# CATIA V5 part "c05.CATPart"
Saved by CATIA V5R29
Part number: c05
Bounding box of the stored display mesh (mm): x 16.662 to 134.073, y -101 to 75, z 102.292 to 225.053
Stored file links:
  C:\Users\제5강의실-23\Desktop\c05.CATPart
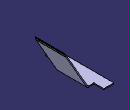
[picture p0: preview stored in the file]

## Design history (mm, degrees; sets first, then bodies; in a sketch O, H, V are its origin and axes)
Body1 (main body)
  DatumCurve1
  DatumSurface1
  DatumSurface2
  Sketch1 on zx-plane, origin (0, 0, 0), H (-1, 0, 0), V (0, 0, 1)
    line L1 (-136.6713, 223.5526) -> (-66.6616, 102.2922)
    line L2 (-66.6616, 102.2922) -> (-16.6616, 102.2922)
    line L3 (-16.6616, 102.2922) -> (-16.6616, 105.2922)
    line L4 (-16.6616, 105.2922) -> (-64.9296, 105.2922)
    line L5 (-64.9296, 105.2922) -> (-134.0732, 225.0526)
    point P6 (-134.0732, 225.0526)
    line L6 (-134.0732, 225.0526) -> (-136.6713, 223.5526)
    reference projected point E1 (-36.6616, 12.2922) from edge of DatumCurve1
    reference intersected line E2 through (0, 102.2922) direction (-1, 0) from face of DatumSurface1
    reference intersected line E3 through (-16.6616, 0) direction (0, 1) from face of DatumSurface2
    length L6 = 3
    length L3 = 3
    length L2 = 50
    angle L1 L2 = 120
    distance P6 E1 = 234
    distance L2 E2 = 0
    horizontal: L2 H, L4 H
    vertical: L3 V
    parallelism: L5 L1
    perpendicularity: L6 L1
    coincidence: L3 E3
  Pad1: profile Sketch1, direction (0, 1, 0), length 45, mirrored extent
  DatumSurface3
  DatumSurface4
  Sketch2 on face of Pad1 from Sketch1.L4, origin (0, 0, 105.2922), H (1, 0, 0), V (0, 1, 0)
    line L1 (46.6616, -101) -> (16.6616, -101)
    line L2 (16.6616, -101) -> (16.6616, -45)
    line L3 (16.6616, -45) -> (46.6616, -45)
    line L4 (46.6616, -45) -> (46.6616, -101)
    reference projected line E1 (16.6616, -45) -> (64.9296, -45) from edge [start face of Pad1 | face of Pad1 from Sketch1.L4]
    reference intersected line E2 through (0, -101) direction (1, 0) from face of DatumSurface3
    reference projected line E3 (16.6616, -45) -> (16.6616, 45) from edge [face of Pad1 from Sketch1.L4 | face of Pad1 from Sketch1.L3]
    point P5 (16.6616, 45)
    line L5 (16.6616, 45) -> (46.6616, 45)
    line L6 (46.6616, 45) -> (46.6616, 75)
    line L7 (46.6616, 75) -> (16.6616, 75)
    line L8 (16.6616, 75) -> (16.6616, 45)
    reference intersected line E4 (16.6616, 45) -> (68.3937, 45) from end face of Pad1
    reference intersected line E5 through (0, 75) direction (-1, 0) from face of DatumSurface4
    distance E2 L1 = 0
    distance L2 E3 = 0
    length L1 = 30
    horizontal: L1 H, L3 H, L5 H, L7 H
    vertical: L2 V, L4 V, L6 V, L8 V
    coincidence: L3 E1, P5 L2, L5 E4, L7 E5, L6 L4
  Pad2: profile Sketch2, direction (0, 0, -1), length 3
  Sketch3 on end face of Pad1, origin (0, 45, 0), H (-1, 0, 0), V (0, 0, 1)
    point P1 (-134.0732, 225.0526)
    line L1 (-134.0732, 225.0526) -> (-131.6713, 214.8924)
    line L2 (-131.6713, 214.8924) -> (-136.6713, 223.5526)
    line L3 (-136.6713, 223.5526) -> (-134.0732, 225.0526)
    reference intersected line E1 (-136.6713, 223.5526) -> (-134.0732, 225.0526) from face of Pad1 from Sketch1.L6
    reference intersected line E2 (-66.6616, 102.2922) -> (-136.6713, 223.5526) from face of Pad1 from Sketch1.L1
    reference intersected line E3 (-134.0732, 225.0526) -> (-64.9296, 105.2922) from face of Pad1 from Sketch1.L5
    length L2 = 10
    coincidence: L3 E1, E2 L2, P1 E3
  Pocket1: profile Sketch3, direction (0, -1, 0), through (limit type 3)
  Sketch4 on face of Pad1 from Sketch1.L1, origin (5.7024, 0, -3.2923), H (0, 1, 0), V (0.5, 0, 0.866)
    point P1 (-45, 261.9379)
    line L1 (-45, 261.9379) -> (-43, 255.9379)
    point P2 (-43, 255.9379)
    line L2 (-43, 255.9379) -> (-43, 261.9379)
    point P3 (-43, 261.9379)
    reference projected line E1 (45, 261.9379) -> (-45, 261.9379) from edge [face of Pad1 from Sketch1.L5 | face of Pocket1 from Sketch3.L1]
    reference projected line E2 (45, 261.9379) -> (-45, 261.9379) from edge [face of Pad1 from Sketch1.L5 | face of Pocket1 from Sketch3.L1]
    reference intersected line E3 (-45, 121.9185) -> (-45, 261.9379) from start face of Pad1
    point P4 (-41, 261.9379)
    point P5 (-41, 255.9379)
    line L3 (-41, 255.9379) -> (-41, 261.9379)
    point P6 (-43, 261.9379)
    line L4 (-43, 261.9379) -> (-41, 255.9379)
    point P7 (-39, 261.9379)
    line L5 (-39, 255.9379) -> (-39, 261.9379)
    point P9 (-41, 261.9379)
    line L6 (-41, 261.9379) -> (-39, 255.9379)
    point P10 (-37, 261.9379)
    line L7 (-37, 255.9379) -> (-37, 261.9379)
    point P12 (-39, 261.9379)
    line L8 (-39, 261.9379) -> (-37, 255.9379)
    point P13 (-35, 261.9379)
    line L9 (-35, 255.9379) -> (-35, 261.9379)
    point P15 (-37, 261.9379)
    line L10 (-37, 261.9379) -> (-35, 255.9379)
    point P16 (-33, 261.9379)
    line L11 (-33, 255.9379) -> (-33, 261.9379)
    point P18 (-35, 261.9379)
    line L12 (-35, 261.9379) -> (-33, 255.9379)
    point P19 (-31, 261.9379)
    line L13 (-31, 255.9379) -> (-31, 261.9379)
    point P21 (-33, 261.9379)
    line L14 (-33, 261.9379) -> (-31, 255.9379)
    point P22 (-29, 261.9379)
    line L15 (-29, 255.9379) -> (-29, 261.9379)
    point P24 (-31, 261.9379)
    line L16 (-31, 261.9379) -> (-29, 255.9379)
    point P25 (-27, 261.9379)
    line L17 (-27, 255.9379) -> (-27, 261.9379)
    point P27 (-29, 261.9379)
    line L18 (-29, 261.9379) -> (-27, 255.9379)
    point P28 (-25, 261.9379)
    line L19 (-25, 255.9379) -> (-25, 261.9379)
    point P30 (-27, 261.9379)
    line L20 (-27, 261.9379) -> (-25, 255.9379)
    point P31 (-23, 261.9379)
    line L21 (-23, 255.9379) -> (-23, 261.9379)
    point P33 (-25, 261.9379)
    line L22 (-25, 261.9379) -> (-23, 255.9379)
    point P34 (-21, 261.9379)
    line L23 (-21, 255.9379) -> (-21, 261.9379)
    point P36 (-23, 261.9379)
    line L24 (-23, 261.9379) -> (-21, 255.9379)
    point P37 (-19, 261.9379)
    line L25 (-19, 255.9379) -> (-19, 261.9379)
    point P39 (-21, 261.9379)
    line L26 (-21, 261.9379) -> (-19, 255.9379)
    point P40 (-17, 261.9379)
    line L27 (-17, 255.9379) -> (-17, 261.9379)
    point P42 (-19, 261.9379)
    line L28 (-19, 261.9379) -> (-17, 255.9379)
    point P43 (-15, 261.9379)
    line L29 (-15, 255.9379) -> (-15, 261.9379)
    point P45 (-17, 261.9379)
    line L30 (-17, 261.9379) -> (-15, 255.9379)
    point P46 (-13, 261.9379)
    line L31 (-13, 255.9379) -> (-13, 261.9379)
    point P48 (-15, 261.9379)
    line L32 (-15, 261.9379) -> (-13, 255.9379)
    point P49 (-11, 261.9379)
    line L33 (-11, 255.9379) -> (-11, 261.9379)
    point P51 (-13, 261.9379)
    line L34 (-13, 261.9379) -> (-11, 255.9379)
    point P52 (-9, 261.9379)
    line L35 (-9, 255.9379) -> (-9, 261.9379)
    point P54 (-11, 261.9379)
    line L36 (-11, 261.9379) -> (-9, 255.9379)
    point P55 (-7, 261.9379)
    line L37 (-7, 255.9379) -> (-7, 261.9379)
    point P57 (-9, 261.9379)
    line L38 (-9, 261.9379) -> (-7, 255.9379)
    point P58 (-5, 261.9379)
    line L39 (-5, 255.9379) -> (-5, 261.9379)
    point P60 (-7, 261.9379)
    line L40 (-7, 261.9379) -> (-5, 255.9379)
    point P61 (-3, 261.9379)
    line L41 (-3, 255.9379) -> (-3, 261.9379)
    point P63 (-5, 261.9379)
    line L42 (-5, 261.9379) -> (-3, 255.9379)
    point P64 (-1, 261.9379)
    line L43 (-1, 255.9379) -> (-1, 261.9379)
    point P66 (-3, 261.9379)
    line L44 (-3, 261.9379) -> (-1, 255.9379)
    point P67 (1, 261.9379)
    line L45 (1, 255.9379) -> (1, 261.9379)
    point P69 (-1, 261.9379)
    line L46 (-1, 261.9379) -> (1, 255.9379)
    point P70 (3, 261.9379)
    line L47 (3, 255.9379) -> (3, 261.9379)
    point P72 (1, 261.9379)
    line L48 (1, 261.9379) -> (3, 255.9379)
    point P73 (5, 261.9379)
    line L49 (5, 255.9379) -> (5, 261.9379)
    point P75 (3, 261.9379)
    line L50 (3, 261.9379) -> (5, 255.9379)
    point P76 (7, 261.9379)
    line L51 (7, 255.9379) -> (7, 261.9379)
    point P78 (5, 261.9379)
    line L52 (5, 261.9379) -> (7, 255.9379)
    point P79 (9, 261.9379)
    line L53 (9, 255.9379) -> (9, 261.9379)
    point P81 (7, 261.9379)
    line L54 (7, 261.9379) -> (9, 255.9379)
    point P82 (11, 261.9379)
    line L55 (11, 255.9379) -> (11, 261.9379)
    point P84 (9, 261.9379)
    line L56 (9, 261.9379) -> (11, 255.9379)
    point P85 (13, 261.9379)
    line L57 (13, 255.9379) -> (13, 261.9379)
    point P87 (11, 261.9379)
    line L58 (11, 261.9379) -> (13, 255.9379)
    point P88 (15, 261.9379)
    line L59 (15, 255.9379) -> (15, 261.9379)
    point P90 (13, 261.9379)
    line L60 (13, 261.9379) -> (15, 255.9379)
    point P91 (17, 261.9379)
    line L61 (17, 255.9379) -> (17, 261.9379)
    point P93 (15, 261.9379)
    line L62 (15, 261.9379) -> (17, 255.9379)
    point P94 (19, 261.9379)
    line L63 (19, 255.9379) -> (19, 261.9379)
    point P96 (17, 261.9379)
    line L64 (17, 261.9379) -> (19, 255.9379)
    point P97 (21, 261.9379)
    line L65 (21, 255.9379) -> (21, 261.9379)
    point P99 (19, 261.9379)
    line L66 (19, 261.9379) -> (21, 255.9379)
    point P100 (23, 261.9379)
    line L67 (23, 255.9379) -> (23, 261.9379)
    point P102 (21, 261.9379)
    line L68 (21, 261.9379) -> (23, 255.9379)
    point P103 (25, 261.9379)
    line L69 (25, 255.9379) -> (25, 261.9379)
    point P105 (23, 261.9379)
    line L70 (23, 261.9379) -> (25, 255.9379)
    point P106 (27, 261.9379)
    line L71 (27, 255.9379) -> (27, 261.9379)
    point P108 (25, 261.9379)
    line L72 (25, 261.9379) -> (27, 255.9379)
    point P109 (29, 261.9379)
    line L73 (29, 255.9379) -> (29, 261.9379)
    point P111 (27, 261.9379)
    line L74 (27, 261.9379) -> (29, 255.9379)
    point P112 (31, 261.9379)
    line L75 (31, 255.9379) -> (31, 261.9379)
    point P114 (29, 261.9379)
    line L76 (29, 261.9379) -> (31, 255.9379)
    point P115 (33, 261.9379)
    line L77 (33, 255.9379) -> (33, 261.9379)
    point P117 (31, 261.9379)
    line L78 (31, 261.9379) -> (33, 255.9379)
    point P118 (35, 261.9379)
    line L79 (35, 255.9379) -> (35, 261.9379)
    point P120 (33, 261.9379)
    line L80 (33, 261.9379) -> (35, 255.9379)
    point P121 (37, 261.9379)
    line L81 (37, 255.9379) -> (37, 261.9379)
    point P123 (35, 261.9379)
    line L82 (35, 261.9379) -> (37, 255.9379)
    point P124 (39, 261.9379)
    line L83 (39, 255.9379) -> (39, 261.9379)
    point P126 (37, 261.9379)
    line L84 (37, 261.9379) -> (39, 255.9379)
    point P127 (41, 261.9379)
    line L85 (41, 255.9379) -> (41, 261.9379)
    point P129 (39, 261.9379)
    line L86 (39, 261.9379) -> (41, 255.9379)
    point P130 (43, 261.9379)
    line L87 (43, 255.9379) -> (43, 261.9379)
    point P132 (41, 261.9379)
    line L88 (41, 261.9379) -> (43, 255.9379)
    point P133 (45, 261.9379)
    point P134 (45, 255.9379)
    line L89 (45, 255.9379) -> (45, 269.2814)
    point P135 (43, 261.9379)
    line L90 (43, 261.9379) -> (45, 255.9379)
    point P136 (47, 261.9379)
    point P137 (45, 261.9379)
    point P140 (-45, 261.9379)
    line L91 (-45, 261.9379) -> (-45, 269.2814)
    line L92 (-45, 269.2814) -> (45, 269.2814)
    distance P3 P1 = 2
    distance P4 P6 = 2
    length L5 = 6
    distance P7 P9 = 2
    length L7 = 6
    distance P10 P12 = 2
    length L9 = 6
    distance P13 P15 = 2
    length L11 = 6
    distance P16 P18 = 2
    length L13 = 6
    distance P19 P21 = 2
    length L15 = 6
    distance P22 P24 = 2
    length L17 = 6
    distance P25 P27 = 2
    length L19 = 6
    distance P28 P30 = 2
    length L21 = 6
    distance P31 P33 = 2
    length L23 = 6
    distance P34 P36 = 2
    length L25 = 6
    distance P37 P39 = 2
    length L27 = 6
    distance P40 P42 = 2
    distance P43 P45 = 2
    length L29 = 6
    length L31 = 6
    distance P46 P48 = 2
    length L33 = 6
    distance P49 P51 = 2
    length L35 = 6
    distance P52 P54 = 2
    length L37 = 6
    distance P55 P57 = 2
    length L39 = 6
    distance P58 P60 = 2
    length L41 = 6
    distance P61 P63 = 2
    length L43 = 6
    distance P64 P66 = 2
    length L45 = 6
    distance P67 P69 = 2
    length L47 = 6
    distance P70 P72 = 2
    length L49 = 6
    distance P73 P75 = 2
    distance P76 P78 = 2
    length L51 = 6
    length L53 = 6
    distance P79 P81 = 2
    length L55 = 6
    distance P82 P84 = 2
    length L57 = 6
    distance P85 P87 = 2
    length L59 = 6
    distance P88 P90 = 2
    length L61 = 6
    distance P91 P93 = 2
    length L63 = 6
    distance P94 P96 = 2
    distance P97 P99 = 2
    length L65 = 6
    length L67 = 6
    distance P100 P102 = 2
    length L69 = 6
    distance P103 P105 = 2
    distance P106 P108 = 2
    length L71 = 6
    distance P109 P111 = 2
    length L73 = 6
    distance P112 P114 = 2
    length L75 = 6
    distance P115 P117 = 2
    length L77 = 6
    distance P118 P120 = 2
    length L79 = 6
    length L81 = 6
    distance P121 P123 = 2
    length L83 = 6
    distance P124 P126 = 2
    distance P127 P129 = 2
    length L85 = 6
    distance P130 P132 = 2
    length L87 = 6
    distance P133 P135 = 2
    distance P136 P137 = 2
    distance P2 P3 = 6
    distance P5 P4 = 6
    distance P134 P133 = 6
    vertical: L2 V, L3 V, L5 V, L7 V, L9 V, L11 V, L13 V, L15 V, L17 V, L19 V, L21 V, L23 V, L25 V, L27 V, L29 V, L31 V, L33 V, L35 V, L37 V, L39 V, L41 V, L43 V, L45 V, L47 V, L49 V, L51 V, L53 V, L55 V, L57 V, L59 V, L61 V, L63 V, L65 V, L67 V, L69 V, L71 V, L73 V, L75 V, L77 V, L79 V, L81 V, L83 V, L85 V, L87 V, L89 V, L91 V
    coincidence: P3 E1, P1 E2, P1 E3, P6 L4, P3 L2, P5 L4, P5 L3, P133 L89, P1 P140, P4 P9, P7 P12, P10 P15, P13 P18, P16 P21, P19 P24, P22 P27, P25 P30, P28 P33, P31 P36, P34 P39, P37 P42, P40 P45, P43 P48, P46 P51, P49 P54, P52 P57, P55 P60, P58 P63, P61 P66, P64 P69, P67 P72, P70 P75, P73 P78, P76 P81, P79 P84, P82 P87, P85 P90, P88 P93, P91 P96, P94 P99, P97 P102, P100 P105, P103 P108, P106 P111, P109 P114, P112 P117, P115 P120, P118 P123, P121 P126, P124 P129, P127 P132, P130 P135
    horizontal: L92 H
  Pocket2: profile Sketch4, direction (-0.866, 0, 0.5), through (limit type 3)
  Fillet1: radius 5, on edge [face of Pocket1 from Sketch3.L1 | face of Pad1 from Sketch1.L1]; edge [face of Pad1 from Sketch1.L5 | face of Pad2]; edge [face of Pad2 | face of Pad1 from Sketch1.L1]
